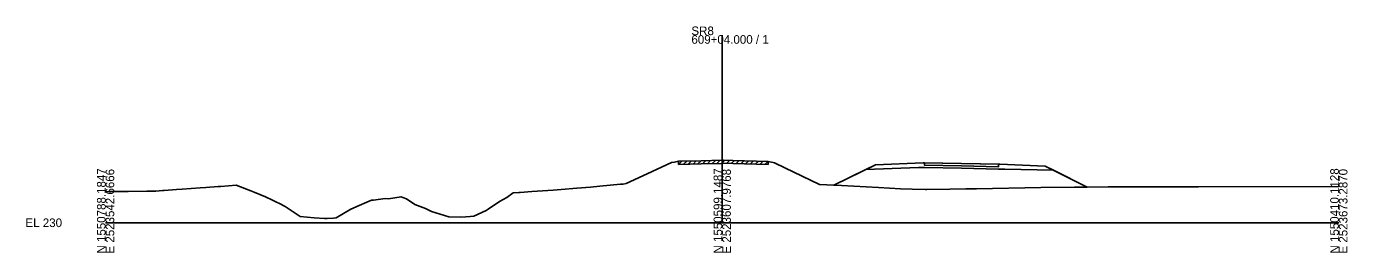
# Model space of a CAD drawing. Extents: x -26 to 2803, y -10 to 19537.
# Drawn here: x -25.7 to 402.8, y 14990.3 to 15063.8 of the extents above; entities that cross this region are included whole.
import ezdxf

# ---------------------------------------------------------------- set-up
doc = ezdxf.new("R2010")
doc.units = 0
for name, color, linetype in [('50', 7, 'Continuous'), ('XS_CELL', 7, 'Continuous'), ('XS_M_MULTI', 7, 'Continuous'), ('XS_M_SHAPES_EARTHWORK', 7, 'Continuous'), ('XS_P_FINISHED_GRADE', 7, 'Continuous'), ('XS_P_SUBGRADE_GRANULAR', 7, 'Continuous'), ('XS_P_SUBGRADE_PAVEMENT', 7, 'Continuous'), ('XS_X_GROUND', 7, 'Continuous')]:
    doc.layers.add(name, color=color, linetype=linetype)

msp = doc.modelspace()

# ---------------------------------------------------------------- linework, layer by layer
at = {"layer": '50'}
for p, q in [((190.53, 15019.08), (191.59, 15020.1)), ((192.08, 15019.11), (193.14, 15020.14)), ((193.63, 15019.15), (194.69, 15020.18)), ((195.19, 15019.19), (196.25, 15020.21)), ((196.74, 15019.22), (197.8, 15020.25)), ((198.29, 15019.26), (199.35, 15020.29)), ((199.84, 15019.3), (200.88, 15020.3)), ((201.39, 15019.29), (202.4, 15020.26)), ((202.95, 15019.25), (203.95, 15020.22)), ((204.5, 15019.21), (205.51, 15020.18)), ((206.05, 15019.17), (207.06, 15020.14)), ((207.6, 15019.13), (208.61, 15020.1)), ((185.87, 15018.97), (186.93, 15019.99)), ((185.87, 15018.97), (185.87, 15019.97)), ((185.87, 15018.97), (193.2, 15019.14)), ((187.43, 15019), (188.49, 15020.03)), ((188.98, 15019.04), (190.04, 15020.07)), ((193.2, 15019.14), (200, 15019.3)), ((200, 15019.3), (200.46, 15019.31)), ((200.46, 15019.31), (203.44, 15019.23)), ((203.44, 15019.23), (214.85, 15018.94)), ((209.16, 15019.09), (210.16, 15020.06)), ((210.71, 15019.05), (211.72, 15020.02)), ((212.26, 15019.01), (213.27, 15019.98)), ((213.81, 15018.97), (214.82, 15019.94)), ((214.85, 15019.94), (214.85, 15018.94))]:
    msp.add_line(p, q, dxfattribs=at)
at = {"layer": 'XS_CELL'}
for p, q in [((200, 15000), (200, 15060.94)), ((0, 15000), (200, 15000)), ((200, 15000), (400, 15000))]:
    msp.add_line(p, q, dxfattribs=at)
at = {"layer": 'XS_M_MULTI'}
for p, q in [((236.17, 15012.18), (249.73, 15018.83)), ((249.73, 15018.83), (265.22, 15019.43)), ((265.22, 15019.43), (277.65, 15019.2)), ((277.65, 15019.2), (290.07, 15018.98)), ((290.07, 15018.98), (304.8, 15018.41)), ((304.8, 15018.41), (318.42, 15011.6))]:
    msp.add_line(p, q, dxfattribs=at)
for points in [[(0, 15010.09), (1.34, 15010.11), (6.37, 15010.16), (7.29, 15010.17), (13.38, 15010.23), (16.31, 15010.26), (18.41, 15010.43), (18.99, 15010.47), (23.04, 15010.77), (24.87, 15010.91), (27.76, 15011.12), (30.71, 15011.33), (32.53, 15011.47), (36.5, 15011.75), (37.37, 15011.82), (42.31, 15012.17), (47.08, 15010.39), (48.17, 15009.9), (51.85, 15008.47), (54.14, 15007.38), (55.41, 15006.7), (56.43, 15006.22), (58.19, 15005.29), (62.49, 15002.48), (63.15, 15002.02), (67.68, 15001.62), (71.02, 15001.38), (71.85, 15001.42), (73.95, 15001.52), (74.75, 15001.56), (79.52, 15004.46), (82.29, 15005.59), (84.76, 15006.69), (86.26, 15007.37), (86.92, 15007.32), (90.7, 15007.88), (91.75, 15007.78), (95.81, 15008.47), (96.4, 15008.22), (97.61, 15007.72), (100.33, 15005.92), (103.76, 15004.67), (105.74, 15003.65), (111.32, 15001.93), (115.03, 15001.86), (116.81, 15001.9), (118.28, 15002.05), (119.46, 15002.16), (123.41, 15003.95), (124.13, 15004.43), (127.79, 15006.86), (130.1, 15008.16), (132.15, 15009.75), (134.05, 15009.82), (134.41, 15009.82), (138.29, 15010.16), (145.21, 15010.62), (147.74, 15010.84), (152.89, 15011.2), (157.3, 15011.61), (160.35, 15011.84), (166.99, 15012.51), (167.82, 15012.57), (168.89, 15012.71), (175.62, 15015.84), (183.59, 15019.56), (184.53, 15019.73), (185.87, 15019.97), (193.2, 15020.14), (200, 15020.3), (200.46, 15020.31), (203.44, 15020.23), (214.85, 15019.94), (216.51, 15019.58), (216.98, 15019.47), (220.33, 15017.86), (231.55, 15012.4), (236.17, 15012.18)], [(318.42, 15011.6), (325.2, 15011.65), (354.53, 15011.72), (400, 15011.78)]]:
    msp.add_lwpolyline(points, dxfattribs=at)
at = {"layer": 'XS_M_SHAPES_EARTHWORK'}
for points in [[(257.82, 15011.07), (261.66, 15010.87), (265.91, 15010.77), (266.35, 15010.76), (273.82, 15010.9), (278.98, 15011), (282.53, 15011.06), (303.39, 15011.49), (318.42, 15011.6), (307.4, 15017.11), (291.65, 15017.42), (289.65, 15017.46), (277.65, 15017.7), (265.65, 15017.94), (263.65, 15017.98), (246.62, 15017.3), (236.17, 15012.18), (238.64, 15012.06), (250.65, 15011.44)], [(289.65, 15017.46), (291.65, 15017.42), (307.4, 15017.11), (304.8, 15018.41), (290.07, 15018.98), (289.65, 15018.99), (289.65, 15018.21), (277.65, 15018.45), (265.65, 15018.69), (265.65, 15019.42), (265.22, 15019.43), (249.73, 15018.83), (246.62, 15017.3), (263.65, 15017.98), (265.65, 15017.94), (277.65, 15017.7)], [(289.65, 15018.21), (289.65, 15018.99), (277.65, 15019.2), (265.65, 15019.42), (265.65, 15018.69), (277.65, 15018.45)]]:
    msp.add_lwpolyline(points, close=True, dxfattribs=at)
at = {"layer": 'XS_P_FINISHED_GRADE'}
for p, q in [((249.73, 15018.83), (236.17, 15012.18)), ((265.22, 15019.43), (249.73, 15018.83)), ((265.22, 15019.43), (277.65, 15019.2)), ((277.65, 15019.2), (290.07, 15018.98)), ((290.07, 15018.98), (304.8, 15018.41)), ((304.8, 15018.41), (318.42, 15011.6))]:
    msp.add_line(p, q, dxfattribs=at)
at = {"layer": 'XS_P_SUBGRADE_GRANULAR'}
for p, q in [((263.65, 15017.98), (246.62, 15017.3)), ((265.65, 15017.94), (263.65, 15017.98)), ((265.65, 15017.94), (277.65, 15017.7)), ((277.65, 15017.7), (289.65, 15017.46)), ((289.65, 15017.46), (291.65, 15017.42)), ((291.65, 15017.42), (307.4, 15017.11))]:
    msp.add_line(p, q, dxfattribs=at)
at = {"layer": 'XS_P_SUBGRADE_PAVEMENT'}
for p, q in [((265.65, 15018.69), (265.65, 15019.42)), ((265.65, 15018.69), (277.65, 15018.45)), ((277.65, 15018.45), (289.65, 15018.21)), ((289.65, 15018.21), (289.65, 15018.99))]:
    msp.add_line(p, q, dxfattribs=at)
at = {"layer": 'XS_X_GROUND'}
msp.add_lwpolyline([(0, 15010.09), (1.34, 15010.11), (6.37, 15010.16), (7.29, 15010.17), (13.38, 15010.23), (16.31, 15010.26), (18.41, 15010.43), (18.99, 15010.47), (23.04, 15010.77), (24.87, 15010.91), (27.76, 15011.12), (30.71, 15011.33), (32.53, 15011.47), (36.5, 15011.75), (37.37, 15011.82), (42.31, 15012.17), (47.08, 15010.39), (48.17, 15009.9), (51.85, 15008.47), (54.14, 15007.38), (55.41, 15006.7), (56.43, 15006.22), (58.19, 15005.29), (62.49, 15002.48), (63.15, 15002.02), (67.68, 15001.62), (71.02, 15001.38), (71.85, 15001.42), (73.95, 15001.52), (74.75, 15001.56), (79.52, 15004.46), (82.29, 15005.59), (84.76, 15006.69), (86.26, 15007.37), (86.92, 15007.32), (90.7, 15007.88), (91.75, 15007.78), (95.81, 15008.47), (96.4, 15008.22), (97.61, 15007.72), (100.33, 15005.92), (103.76, 15004.67), (105.74, 15003.65), (111.32, 15001.93), (115.03, 15001.86), (116.81, 15001.9), (118.28, 15002.05), (119.46, 15002.16), (123.41, 15003.95), (124.13, 15004.43), (127.79, 15006.86), (130.1, 15008.16), (132.15, 15009.75), (134.05, 15009.82), (134.41, 15009.82), (138.29, 15010.16), (145.21, 15010.62), (147.74, 15010.84), (152.89, 15011.2), (157.3, 15011.61), (160.35, 15011.84), (166.99, 15012.51), (167.82, 15012.57), (168.89, 15012.71), (175.62, 15015.84), (183.59, 15019.56), (184.53, 15019.73), (185.87, 15019.97), (193.2, 15020.14), (200, 15020.3), (200.46, 15020.31), (203.44, 15020.23), (214.85, 15019.94), (216.51, 15019.58), (216.98, 15019.47), (220.33, 15017.86), (231.55, 15012.4), (238.64, 15012.06), (250.65, 15011.44), (257.82, 15011.07), (261.66, 15010.87), (265.91, 15010.77), (266.35, 15010.76), (273.82, 15010.9), (278.98, 15011), (282.53, 15011.06), (303.39, 15011.49), (325.2, 15011.65), (354.53, 15011.72), (400, 15011.78)], dxfattribs=at)

# ---------------------------------------------------------------- texts
at = {"layer": 'XS_CELL'}
for s, p in [('SR8', (190, 15060.94)), ('609+04.000 / 1', (190, 15058.14)), ('EL 230', (-26, 14998.6))]:
    msp.add_text(s, height=2.8, dxfattribs=at).set_placement(p)
for s, p in [('N 1550788.1847', (0, 14990)), ('E 2523542.6666', (2.8, 14990)), ('N 1550599.1487', (200, 14990)), ('E 2523607.9768', (202.8, 14990)), ('N 1550410.1128', (400, 14990)), ('E 2523673.2870', (402.8, 14990))]:
    msp.add_text(s, height=2.8, rotation=90, dxfattribs=at).set_placement(p)

doc.saveas('drawing.dxf')
